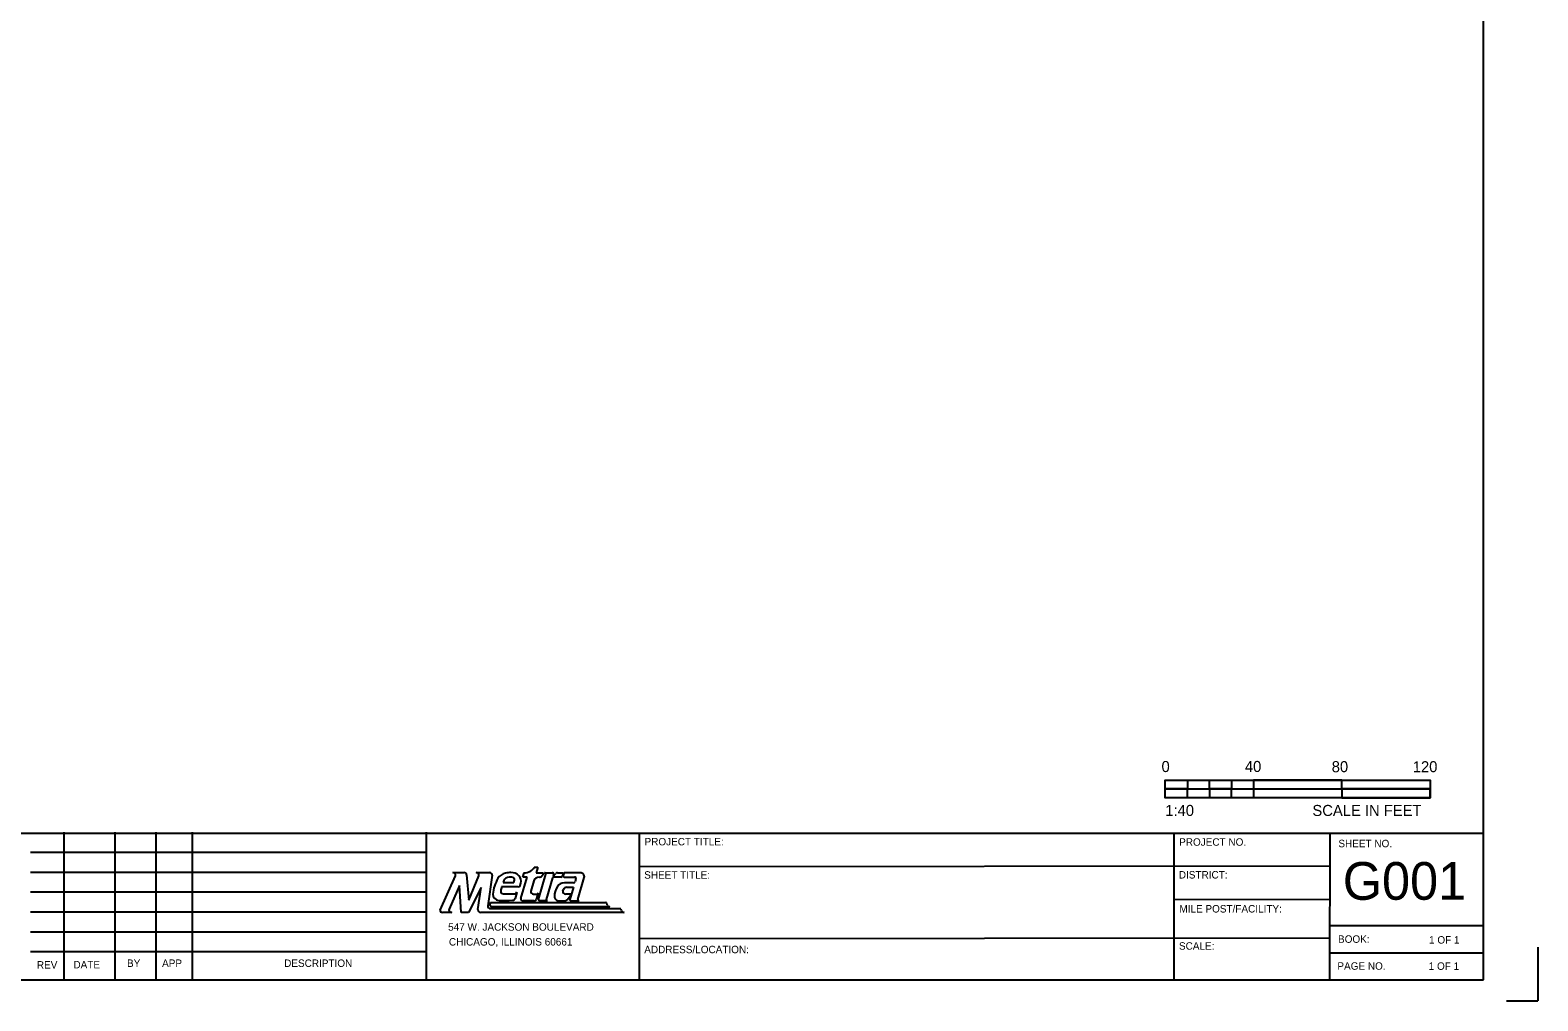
# Model space of a CAD drawing. Extents: x 0 to 34, y 0 to 22.
# Drawn here: x 16.89 to 33.97, y 0 to 10.99 of the extents above; entities that cross this region are included whole.
import ezdxf

# ---------------------------------------------------------------- set-up
doc = ezdxf.new("R2010")
doc.units = 0
for name, color, linetype in [('Level 1', 7, 'Continuous'), ('Level 63', 7, 'Continuous'), ('Sheets_General Details', 7, 'Continuous')]:
    doc.layers.add(name, color=color, linetype=linetype)

msp = doc.modelspace()

# ---------------------------------------------------------------- linework, layer by layer
at = {"layer": 'Level 63'}
for p, q in [((33.353, 0.238), (33.353, 21.739)), ((1.013, 1.9), (33.353, 1.9)), ((17.281, 0.25), (17.281, 1.908)), ((17.858, 0.25), (17.858, 1.908)), ((18.322, 0.25), (18.322, 1.908)), ((18.733, 0.25), (18.733, 1.908)), ((21.383, 0.25), (21.383, 1.908)), ((23.793, 1.9), (23.793, 0.238)), ((29.847, 1.9), (29.847, 0.238)), ((31.611, 1.899), (31.61, 0.238)), ((16.897, 1.683), (21.383, 1.683)), ((16.897, 1.458), (21.383, 1.458)), ((21.536, 1.028), (21.711, 1.415)), ((21.682, 1.454), (21.805, 1.454)), ((21.837, 1.427), (21.861, 1.141)), ((21.861, 1.141), (21.975, 1.417)), ((21.945, 1.454), (22.096, 1.454)), ((22.128, 1.422), (22.077, 1.076)), ((22.349, 1.399), (22.319, 1.399)), ((22.451, 1.159), (22.522, 1.402)), ((22.473, 1.402), (22.488, 1.45)), ((22.522, 1.402), (22.473, 1.402)), ((22.604, 1.512), (22.643, 1.512)), ((22.643, 1.512), (22.625, 1.45)), ((22.625, 1.45), (22.706, 1.45)), ((22.65, 1.148), (22.733, 1.433)), ((22.662, 1.402), (22.667, 1.402)), ((22.706, 1.45), (22.699, 1.422)), ((22.718, 1.45), (22.806, 1.45)), ((22.733, 1.433), (22.733, 1.433)), ((22.733, 1.433), (22.733, 1.433)), ((22.81, 1.391), (22.739, 1.148)), ((22.816, 1.409), (22.849, 1.442)), ((22.823, 1.433), (22.816, 1.409)), ((22.906, 1.402), (22.826, 1.402)), ((22.867, 1.45), (22.933, 1.45)), ((22.912, 1.403), (22.921, 1.412)), ((22.933, 1.45), (22.921, 1.412)), ((22.932, 1.448), (22.931, 1.45)), ((22.941, 1.45), (22.932, 1.419)), ((23.121, 1.45), (22.941, 1.45)), ((22.947, 1.402), (23.06, 1.402)), ((23.075, 1.384), (23.065, 1.346)), ((23.095, 1.148), (23.169, 1.398)), ((23.792, 1.522), (31.608, 1.528)), ((16.897, 1.233), (21.383, 1.233)), ((21.758, 1.306), (21.638, 1.039)), ((21.777, 1.002), (21.758, 1.306)), ((22.002, 1.285), (21.857, 1.002)), ((21.965, 1.033), (22.002, 1.285)), ((22.421, 1.291), (22.234, 1.291)), ((22.25, 1.339), (22.373, 1.339)), ((22.256, 1.211), (22.375, 1.211)), ((22.373, 1.339), (22.381, 1.365)), ((22.405, 1.227), (22.386, 1.159)), ((22.406, 1.228), (22.406, 1.229)), ((22.406, 1.228), (22.406, 1.229)), ((22.445, 1.306), (22.452, 1.333)), ((22.452, 1.333), (22.452, 1.332)), ((22.452, 1.332), (22.452, 1.333)), ((22.599, 1.36), (22.565, 1.242)), ((22.595, 1.207), (22.628, 1.207)), ((22.646, 1.222), (22.625, 1.148)), ((22.644, 1.214), (22.643, 1.216)), ((22.87, 1.301), (22.887, 1.317)), ((22.928, 1.242), (22.934, 1.261)), ((23.049, 1.336), (22.945, 1.336)), ((23.024, 1.207), (22.96, 1.207)), ((22.973, 1.287), (23.047, 1.287)), ((22.977, 1.144), (23.024, 1.207)), ((23.047, 1.287), (23.006, 1.148)), ((22.104, 1.081), (22.109, 1.114)), ((22.109, 1.114), (23.414, 1.114)), ((22.11, 1.044), (23.579, 1.044)), ((23.459, 1.066), (22.119, 1.066)), ((22.601, 1.131), (22.476, 1.131)), ((22.755, 1.131), (22.665, 1.131)), ((22.888, 1.131), (22.95, 1.131)), ((23.022, 1.131), (23.112, 1.131)), ((23.42, 1.11), (23.427, 1.087)), ((23.585, 1.041), (23.589, 1.022)), ((29.842, 1.149), (31.611, 1.15)), ((16.897, 1.008), (21.383, 1.008)), ((21.669, 1.002), (21.564, 1.002)), ((21.663, 1.002), (21.662, 1.003)), ((21.857, 1.002), (21.777, 1.002)), ((23.621, 1.002), (21.997, 1.002)), ((23.619, 1.002), (23.62, 1.002)), ((16.897, 0.783), (21.383, 0.783)), ((31.612, 0.711), (23.793, 0.701)), ((31.613, 0.852), (33.359, 0.852)), ((16.897, 0.557), (21.383, 0.557)), ((31.61, 0.545), (33.357, 0.545)), ((33.968, 0.609), (33.968, 0)), ((1.013, 0.238), (33.353, 0.238)), ((33.612, 0), (33.968, 0))]:
    msp.add_line(p, q, dxfattribs=at)
for centre, major_axis, ratio, start_param, end_param in [((21.681, 1.425), (0.0324, 0), 0.853848, 5.915989, 7.853982), ((21.805, 1.425), (0.0324, 0), 0.853848, 0.071033, 1.570796), ((21.945, 1.425), (0.0324, 0), 0.853848, 5.943998, 7.853982), ((22.096, 1.425), (0.0324, 0), 0.853848, 6.159222, 7.853982), ((22.715, 1.167), (0.583, 0), 0.853848, 2.683671, 3.058115), ((22.309, 1.338), (0.13, 0), 0.853848, 1.819476, 2.683671), ((22.32, 1.343), (0.0648, 0), 0.853848, 1.570796, 2.788449), ((22.348, 1.204), (0.292, 0), 0.853848, 1.605654, 1.819476), ((22.342, 1.356), (0.113, 0), 0.853848, 6.038576, 7.88884), ((22.349, 1.371), (0.0324, 0), 0.853848, 6.038262, 7.853982), ((22.487, 1.56), (0.13, 0), 0.853848, 4.712264, 5.830369), ((22.661, 1.346), (-0.0648, 0), 0.853848, 4.712389, 6.037815), ((22.666, 1.429), (0.0324, 0), 0.853848, 4.712389, 6.038063), ((22.718, 1.436), (0.0162, 0), 0.853848, 6.037816, 7.853982), ((22.807, 1.436), (0.0162, 0), 0.853848, 6.037783, 7.853982), ((22.826, 1.387), (-0.0162, 0), 0.853848, 4.712389, 6.037802), ((22.867, 1.429), (-0.0243, 0), 0.853848, 4.712389, 5.588447), ((22.906, 1.415), (0.0162, 0), 0.853848, 4.712389, 6.038551), ((22.947, 1.415), (-0.0162, 0), 0.853848, 6.038336, 7.853982), ((23.06, 1.387), (0.0162, 0), 0.853848, 6.03784, 7.853982), ((23.122, 1.408), (0.0486, 0), 0.853848, 6.038559, 7.853982), ((22.211, 1.203), (0.0769, 0), 0.853848, 3.058115, 4.617236), ((22.256, 1.239), (-0.0324, 0), 0.853848, 6.143474, 7.853982), ((22.897, 1.162), (0.68, 0), 0.853848, 2.918111, 3.001882), ((22.897, 1.162), (0.68, 0), 0.853848, 2.788449, 2.831697), ((22.375, 1.239), (0.0324, 0), 0.853848, 4.712389, 6.0389), ((22.421, 1.311), (-0.0243, 0), 0.853848, 1.570796, 2.896259), ((22.596, 1.235), (-0.0324, 0), 0.853848, 6.038029, 7.853982), ((22.627, 1.227), (-0.0202, 0), 0.975826, 1.570796, 2.862221), ((23.123, 1.177), (-0.292, 0), 0.853848, 5.78818, 6.271188), ((22.944, 1.259), (-0.0891, 0), 0.853848, 4.712389, 5.78818), ((22.96, 1.235), (-0.0324, 0), 0.853848, 6.037776, 7.853982), ((22.973, 1.252), (-0.0405, 0), 0.853848, 4.712389, 6.037594), ((23.049, 1.349), (-0.0162, 0), 0.853848, 1.570796, 2.897441), ((21.563, 1.024), (0.0267, 0), 0.853848, 2.988313, 4.712389), ((21.669, 1.029), (-0.0324, 0), 0.853848, 5.916118, 7.853982), ((21.998, 1.029), (-0.0324, 0), 0.853848, 6.158977, 7.853982), ((22.109, 1.072), (-0.0324, 0), 0.853848, 6.158817, 7.853982), ((22.119, 1.08), (-0.0162, 0), 0.853848, 6.159449, 7.853982), ((22.278, 1.799), (0.778, 0), 0.853848, 4.617236, 4.814934), ((22.354, 1.166), (0.0324, 0), 0.853848, 4.814934, 6.038414), ((22.476, 1.153), (-0.0259, 0), 0.853848, 6.038044, 7.853982), ((22.601, 1.155), (-0.0243, 0), 0.975826, 1.570796, 2.863563), ((22.666, 1.145), (-0.0162, 0), 0.853848, 6.038691, 7.853982), ((22.755, 1.145), (-0.0162, 0), 0.853848, 6.038163, 7.853982), ((22.888, 1.18), (-0.0567, 0), 0.853848, 6.271188, 7.853982), ((22.95, 1.159), (-0.0324, 0), 0.853848, 1.570796, 2.583462), ((23.022, 1.145), (-0.0162, 0), 0.853848, 6.038115, 7.853982), ((23.111, 1.145), (-0.0162, 0), 0.853848, 6.038149, 7.853982), ((23.414, 1.108), (0.00607, 0), 0.853848, 0.25051, 1.570796), ((23.459, 1.093), (0.0324, 0), 0.853848, 3.446267, 4.712389), ((23.578, 1.039), (0.00607, 0), 0.853848, 0.236194, 1.570796), ((23.621, 1.029), (0.0324, 0), 0.853848, 3.439945, 4.712389)]:
    msp.add_ellipse(centre, major_axis=major_axis, ratio=ratio, start_param=start_param, end_param=end_param, dxfattribs=at)
at = {"layer": 'Sheets_General Details'}
msp.add_line((29.749, 2.4), (32.749, 2.4), dxfattribs=at)
for points in [[(32.749, 2.3), (29.749, 2.3), (29.749, 2.5), (32.749, 2.5)], [(29.749, 2.5), (29.999, 2.5), (29.999, 2.4), (29.749, 2.4)], [(29.999, 2.4), (30.249, 2.4), (30.249, 2.3), (29.999, 2.3)], [(30.249, 2.5), (30.499, 2.5), (30.499, 2.4), (30.249, 2.4)], [(30.499, 2.4), (30.749, 2.4), (30.749, 2.3), (30.499, 2.3)], [(30.749, 2.4), (31.749, 2.4), (31.749, 2.5), (30.749, 2.5)], [(31.749, 2.3), (32.749, 2.3), (32.749, 2.4), (31.749, 2.4)]]:
    msp.add_lwpolyline(points, close=True, dxfattribs=at)

# ---------------------------------------------------------------- texts
at = {"layer": 'Level 1'}
msp.add_text('G001', height=0.4271, dxfattribs=at).set_placement((31.759, 1.144))
at = {"layer": 'Level 63'}
for s, height, p in [('PROJECT TITLE:', 0.08439, (23.852, 1.76)), ('PROJECT NO.', 0.08439, (29.906, 1.756)), ('SHEET NO.', 0.0844, (31.709, 1.739)), ('SHEET TITLE:', 0.08439, (23.848, 1.383)), ('DISTRICT:', 0.0844, (29.902, 1.385)), ('MILE POST/FACILITY:', 0.08439, (29.909, 1)), ('547 W. JACKSON BOULEVARD', 0.08439, (21.628, 0.794)), ('CHICAGO, ILLINOIS 60661', 0.08439, (21.637, 0.626)), ('BOOK:', 0.0844, (31.705, 0.657)), ('1 OF 1', 0.0844, (32.736, 0.648)), ('ADDRESS/LOCATION:', 0.08439, (23.849, 0.539)), ('SCALE:', 0.0844, (29.904, 0.579)), ('REV', 0.0844, (16.971, 0.365)), ('DATE', 0.0844, (17.385, 0.367)), ('BY', 0.0844, (17.992, 0.384)), ('APP', 0.0844, (18.389, 0.384)), ('DESCRIPTION', 0.08441, (19.771, 0.384)), ('PAGE NO. ', 0.0844, (31.698, 0.352)), ('1 OF 1', 0.0844, (32.732, 0.351))]:
    msp.add_text(s, height=height, dxfattribs=at).set_placement(p)
at = {"layer": 'Sheets_General Details'}
for s, rotation, p in [('0', 0.4156, (29.707, 2.59)), ('40', 0.4156, (30.651, 2.59)), ('80', 0.3861, (31.634, 2.588)), ('120', 0.4151, (32.552, 2.587))]:
    msp.add_text(s, height=0.125, rotation=rotation, dxfattribs=at).set_placement(p)
for s, p in [('1:40', (29.749, 2.093)), ('SCALE IN FEET', (31.415, 2.093))]:
    msp.add_text(s, height=0.125, dxfattribs=at).set_placement(p)

doc.saveas('drawing.dxf')
